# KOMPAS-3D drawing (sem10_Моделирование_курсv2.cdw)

Views: Вид 1
Referenced files in \\XDEV-LAPTOP\Users\xdev\Desktop\baumanka\sem10\Курсач\pics\АПкурса\: all_pp2.bmp, ie psi.jpg, mu AP.jpg
Referenced files: modelir1.cdw
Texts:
  Автопилот стабилизации угла курса
  Моделирование
  Hornet
  Normal
  Microsoft Sans Serif
  Автопилот стабилизации угла курса ЛА
  (перекрестная схема)
  Передаточная функция замкнутой системы:
  tрег = (10 . . 18)с
  Условие по заданию:
  № реж.
  Параметры автопилота угла курса:
  Зависимость расчетных и аппроксимированных
  передаточных чисел АП от высоты полета:
  Структурная схема системы самолет-АП курса перекрестной схемы
  Переходные процессы на всех режимах полета
  Результаты:
  H, мх10 3
  Пашинин С.А.
  Окоемов Б.Н.
  Автопилот крена-
  МГТУ им. Н.Э.Баумана
  Кафедра ИУ2
  Группа ИУ2-102
Dimensions and other numbers on the sheet: 1; 2; 3; 4; 5; 6; 7; 8; 9; 10; 11; 12; 0,6; 0,9; 0,4; 0,06; 1,65; 0,23; 1,32; 0,62; 2,8; 1,6; 1,5; 4,8; 9,6; 17,5; 10,2; 22,7; 9,7; 18; 24,8; 28; 32; 0; 1:1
